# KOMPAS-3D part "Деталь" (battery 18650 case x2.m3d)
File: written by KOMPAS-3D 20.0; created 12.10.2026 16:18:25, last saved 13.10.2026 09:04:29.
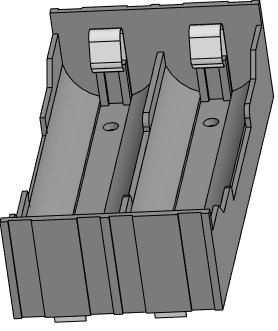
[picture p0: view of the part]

Document properties: Полное имя файла: D:\RicWork\Project-EPS32\box_compas\battery 18650 case x2.m3d

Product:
- Part/product: Деталь
    Масса: 0.123603
  - Body: Тело 1
      Масса: 0.130939

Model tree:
1. Эскиз:1
2. Элемент выдавливания:1
     Расстояние 1 = 21.54
3. Эскиз:2  (with: Элемент выдавливания:1)
4. Элемент выдавливания:2
     Расстояние 2 = 20
5. Эскиз:3  (with: Элемент выдавливания:1)
6. Элемент выдавливания:3
     Расстояние 2 = 21.54
7. Эскиз:4  (with: Элемент выдавливания:1)
8. Элемент выдавливания:4
     Расстояние 2 = 21.54
9. Массив по сетке:1  (with: Элемент выдавливания:4, Эскиз:4)  (4 pattern instances)
     Шаг 1 = 55.62; Угол раствора = -90; Шаг 2 = 19.3; Геометрический массив = 128
10. Эскиз:5  (with: Элемент выдавливания:2)
11. Элемент выдавливания:5
     Расстояние 1 = 9
12. Смещенная плоскость:1  (with: Элемент выдавливания:2)
     Расстояние = -0.605
13. Зеркальный массив:1
14. Экземпляр ( 1 )
15. Экземпляр ( 2 )  (with: Элемент выдавливания:5)
16. Смещенная плоскость:2  (with: Элемент выдавливания:1)
     Расстояние = -38.85
17. Зеркальный массив:2  (with: Экземпляр ( 1 ), Экземпляр ( 2 ), Зеркальный массив:1, Элемент выдавливания:5)
18. Зеркальный массив:3  (with: Экземпляр ( 1 ), Экземпляр ( 2 ), Элемент выдавливания:3)
19. Эскиз:6  (with: Элемент выдавливания:1, Элемент выдавливания:2)
20. Элемент выдавливания:6
     Расстояние 2 = 9.7
21. Эскиз:7  (with: Элемент выдавливания:1)
22. Элемент выдавливания:7
     Расстояние 2 = 40.21
23. Фаска:1  (with: Элемент выдавливания:7)
     Угол = 45; Длина 1 = 4; Длина 2 = 4
24. Скругление:1  (with: Элемент выдавливания:7)
     Радиус = 2
25. Смещенная плоскость:3  (with: Элемент выдавливания:1)
     Расстояние = -7.45
26. Эскиз:8  (with: Элемент выдавливания:2)
27. Элемент выдавливания:8
     Расстояние 2 = 6
28. Зеркальный массив:4  (with: Экземпляр ( 1 ), Экземпляр ( 2 ), Элемент выдавливания:8)
29. Зеркальный массив:5  (with: Экземпляр ( 1 ), Экземпляр ( 2 ), Зеркальный массив:4, Элемент выдавливания:8)
30. Эскиз:9  (with: Элемент выдавливания:2, Элемент выдавливания:6, Элемент выдавливания:7, Элемент выдавливания:8)
31. Элемент выдавливания:11
     Расстояние 1 = 74.7
32. Зеркальный массив:6  (with: Экземпляр ( 1 ), Экземпляр ( 2 ), Элемент выдавливания:11)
